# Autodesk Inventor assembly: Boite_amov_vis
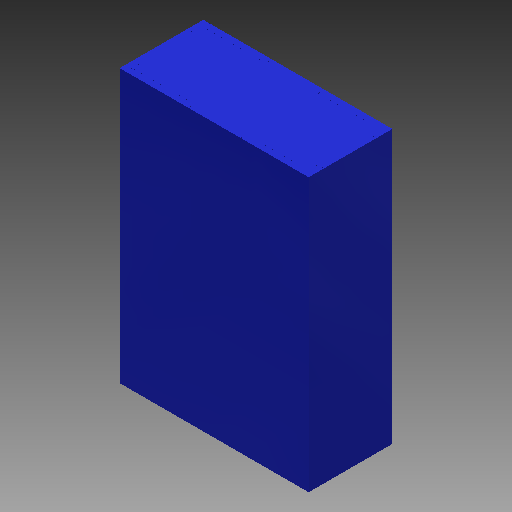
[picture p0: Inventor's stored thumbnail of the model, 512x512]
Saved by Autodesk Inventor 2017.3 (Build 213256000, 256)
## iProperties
Part Number: Boite_amov_vis
Material: Générique
Document SubType Name: Assembly
Designer: ficho
Author: ficho
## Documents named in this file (4)
- G:\travail\année 2019-2020\réforme\avant février\IT\Boite_amov_vis.iam
- G:\travail\année 2019-2020\réforme\avant février\IT\face_amov_vis.ipt
- G:\travail\année 2019-2020\réforme\avant février\IT\Cote_amov_vis.ipt
- G:\travail\année 2019-2020\réforme\avant février\IT\dessus_amov_vis.ipt
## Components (6 placed, 3 different names)
1. face_amov_vis:1 — Affleurement:1, Affleurement:2, Placage:1, Affleurement:4, Affleurement:5, Affleurement:6, Placage:2
2. face_amov_vis:2 — Affleurement:1, Affleurement:2, Placage:1, Affleurement:3, Affleurement:7, Affleurement:9
3. Cote_amov_vis:1 — Affleurement:3, Affleurement:8
4. Cote_amov_vis:2 — Affleurement:4, Affleurement:5, Affleurement:6
5. dessus_amov_vis:1 — Affleurement:7
6. dessus_amov_vis:2 — Placage:2, Affleurement:8, Affleurement:9
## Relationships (11: Flush 9, Mate 2)
- Affleurement:1 [Flush]: face_amov_vis:1 ↔ face_amov_vis:2
- Affleurement:2 [Flush]: face_amov_vis:1 ↔ face_amov_vis:2
- Placage:1 [Mate]: face_amov_vis:1 ↔ face_amov_vis:2
- Affleurement:3 [Flush]: face_amov_vis:2 ↔ Cote_amov_vis:1
- Affleurement:4 [Flush]: face_amov_vis:1 ↔ Cote_amov_vis:2
- Affleurement:5 [Flush]: face_amov_vis:1 ↔ Cote_amov_vis:2
- Affleurement:6 [Flush]: face_amov_vis:1 ↔ Cote_amov_vis:2
- Affleurement:7 [Flush]: face_amov_vis:2 ↔ dessus_amov_vis:1
- Placage:2 [Mate]: face_amov_vis:1 ↔ dessus_amov_vis:2
- Affleurement:8 [Flush]: Cote_amov_vis:1 ↔ dessus_amov_vis:2
- Affleurement:9 [Flush]: face_amov_vis:2 ↔ dessus_amov_vis:2
